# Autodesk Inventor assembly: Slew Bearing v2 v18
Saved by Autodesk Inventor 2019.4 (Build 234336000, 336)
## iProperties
Created: 2020-05
Part Number: Slew Bearing v2 v18
Document SubType Name: Assembly
Designer: Administrator
Title: Slew Bearing v2 v18 v7
Author: Administrator
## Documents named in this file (5)
- c:\worker\convert-fusion-r04\tmp\job-1\518\output\files\f72afacd-c456-4141-9509-cc60ea00d29e\241e21c2-ab76-4c4a-bbe1-8c39d850fb99.iam
- c:\worker\convert-fusion-r04\tmp\job-1\518\output\files\f72afacd-c456-4141-9509-cc60ea00d29e\Rolls A.ipt
- c:\worker\convert-fusion-r04\tmp\job-1\518\output\files\f72afacd-c456-4141-9509-cc60ea00d29e\Rolls B.ipt
- c:\worker\convert-fusion-r04\tmp\job-1\518\output\files\f72afacd-c456-4141-9509-cc60ea00d29e\Race Outer.ipt
- c:\worker\convert-fusion-r04\tmp\job-1\518\output\files\f72afacd-c456-4141-9509-cc60ea00d29e\Race Inner.iam
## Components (4 placed, 4 different names)
1. Rolls A:1
2. Rolls B:1
3. Race Outer:1
4. Race Inner:1 [sub-assembly]
